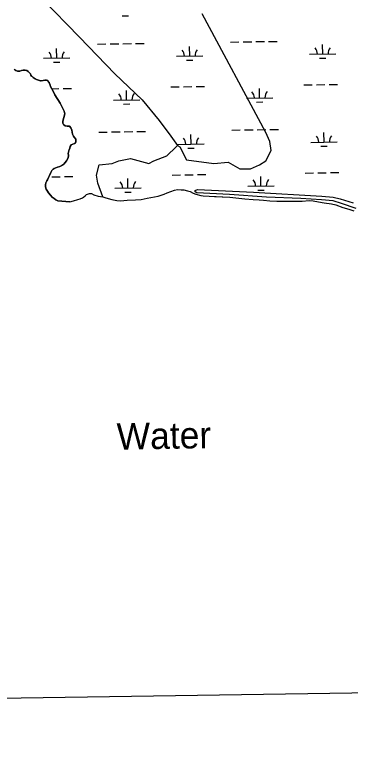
# Model space of a CAD drawing. Extents: x 3812694 to 3850888, y 319753 to 345638.
# Drawn here: x 3828221 to 3829488, y 325178 to 327931 of the extents above; entities that cross this region are included whole.
import ezdxf

# ---------------------------------------------------------------- set-up
doc = ezdxf.new("R2010")
doc.units = 0
for name, color, linetype in [('V-GRID-FRAM', 7, 'Continuous'), ('V-RIVR-IDEN', 7, 'Continuous'), ('V-RIVR-JETY', 7, 'Continuous'), ('V-TOPO-SHOR', 7, 'Continuous'), ('V-WETL-SWMP', 7, 'Continuous')]:
    doc.layers.add(name, color=color, linetype=linetype)

msp = doc.modelspace()

# ---------------------------------------------------------------- linework, layer by layer
at = {"layer": 'V-GRID-FRAM'}
msp.add_lwpolyline([(3816670, 343358.9), (3848499.3, 343840.5), (3848782.3, 325660.2), (3816937.1, 325178.5), (3816670, 343358.9)], dxfattribs=at)
at = {"layer": 'V-RIVR-JETY'}
msp.add_lwpolyline([(3829510.2, 327199.2), (3829453.9, 327218.2), (3829423.1, 327227.1), (3829379.5, 327231.8), (3829300.5, 327236.4), (3829172, 327240.9), (3829032, 327252), (3828908, 327258.4), (3828902, 327262), (3828902, 327267.2), (3828911.2, 327270.6), (3829122.4, 327260), (3829380.5, 327245.1), (3829423.3, 327241.8), (3829450, 327235.5), (3829498.9, 327219.8)], dxfattribs=at)
at = {"layer": 'V-TOPO-SHOR'}
for points in [[(3827576.5, 328656.4), (3827719.1, 328572.8), (3827778.1, 328533.5), (3827832.2, 328474.5), (3827881.4, 328420.4), (3827935.4, 328322.1), (3828033.8, 328248.3), (3828323.8, 327992.7), (3828466.4, 327845.2), (3828599.1, 327707.5), (3828702.4, 327609.2), (3828766.3, 327530.5), (3828810.6, 327471.5), (3828835.1, 327437.1), (3828845, 327432.2)], [(3828845, 327432.2), (3828869.5, 327383), (3828972.8, 327368.3), (3829026.9, 327373.2), (3829071.1, 327348.6), (3829110.5, 327348.6), (3829144.9, 327363.4), (3829169.4, 327378.1), (3829189.1, 327417.4), (3829184.2, 327451.9), (3829169.4, 327486.3), (3828928.5, 327933.7)], [(3828221.8, 327722.9), (3828220.8, 327725.5)], [(3828356.8, 327658.9), (3828354.7, 327664.6), (3828352.1, 327670.2), (3828351.1, 327675.3), (3828349.5, 327676.4), (3828348, 327679.9), (3828346.4, 327681.5), (3828343.9, 327682.5), (3828341.8, 327683), (3828335.6, 327683.5), (3828328.9, 327682.4), (3828321.2, 327680.8), (3828318.2, 327680.3), (3828307.3, 327684.9), (3828303.7, 327685.9), (3828298.6, 327688.9), (3828294.5, 327691.5), (3828291.4, 327693), (3828286.7, 327697.1), (3828284.7, 327699.1), (3828282.6, 327701.7), (3828281, 327706.8), (3828276.4, 327711.9), (3828272.7, 327715.5), (3828267.1, 327719.6), (3828261.4, 327721.1), (3828252.7, 327721.6), (3828247, 327720.5), (3828240.3, 327717.9), (3828235.7, 327716.8), (3828231.6, 327716.8), (3828225.9, 327719.4), (3828221.8, 327722.9)], [(3828428.9, 327224.4), (3828384.4, 327227.3), (3828376.7, 327231.4), (3828370, 327236), (3828362.7, 327241.6), (3828356, 327249.3), (3828349.3, 327258), (3828344.6, 327264.1), (3828340, 327271.3), (3828337.9, 327280.5), (3828337.8, 327287.7), (3828339.3, 327295.4), (3828342.9, 327302.7), (3828345.4, 327307.3), (3828349, 327316.1), (3828352.5, 327323.8), (3828357.1, 327334.6), (3828361.2, 327342.3), (3828366.3, 327347.5), (3828370.4, 327350.1), (3828377, 327352.7), (3828383.2, 327355.3), (3828391.4, 327357.9), (3828399.1, 327361.1), (3828403.7, 327364.2), (3828406.8, 327366.2), (3828410.9, 327371.4), (3828417, 327379.1), (3828421.6, 327387.4), (3828424.6, 327396.1), (3828424.6, 327400.3), (3828423, 327406.4), (3828424, 327410), (3828426, 327417.2), (3828427, 327419.8), (3828429.1, 327426), (3828431.1, 327432.7), (3828434.1, 327439.4), (3828447.5, 327443.6), (3828450.5, 327446.1), (3828452.6, 327450.3), (3828452.5, 327454.4), (3828451.5, 327460), (3828446.3, 327468.2), (3828442.7, 327471.8), (3828439.5, 327480), (3828438.5, 327487.2), (3828436.4, 327494.4), (3828433.2, 327503.6), (3828428.6, 327509.8), (3828425, 327510.2), (3828419.3, 327510.2), (3828411.6, 327510.7), (3828406.5, 327514.3), (3828404.9, 327515.8), (3828403.3, 327520.9), (3828402.8, 327528.1), (3828406.8, 327542), (3828410.3, 327556.4), (3828408.2, 327566.7), (3828393.2, 327595.9), (3828372.4, 327628.2), (3828367.2, 327639.4), (3828361, 327650.7), (3828356.8, 327658.9)], [(3828554, 327242.9), (3828535.2, 327294.5), (3828530.3, 327324), (3828540.2, 327363.4), (3828589.3, 327368.3), (3828613.9, 327378.1), (3828658.1, 327387.9), (3828727, 327368.3), (3828746.6, 327378.1), (3828795.8, 327397.8), (3828830.2, 327432.2), (3828835.1, 327437.1)], [(3828428.9, 327224.4), (3828443.6, 327228.1), (3828459.5, 327233), (3828469, 327235.5), (3828477.2, 327239.1), (3828481.3, 327241.6), (3828487.2, 327246.9), (3828491.9, 327251.1), (3828503.6, 327254.8), (3828510.7, 327254.9), (3828520.3, 327249.7), (3828536.9, 327245.7), (3828554, 327242.9), (3828565.3, 327239.5), (3828588.4, 327233.3), (3828606.2, 327229.3), (3828620.4, 327227.7), (3828645.8, 327229.7), (3828676.6, 327231.3), (3828699, 327233.3), (3828720.8, 327238.2), (3828749.2, 327242.7), (3828762.7, 327245.2), (3828774.5, 327249.5), (3828785.7, 327253.1), (3828796.3, 327258), (3828809.9, 327262.3), (3828824, 327267.7), (3828835.2, 327270.2), (3828849.4, 327269.8), (3828860, 327269.3), (3828873.1, 327265.9), (3828883.2, 327262.5), (3828894.5, 327256.7), (3828905.2, 327253.3), (3828923.5, 327248.1), (3828933, 327246.5), (3828955.5, 327245.5), (3828975, 327244.6), (3829033.6, 327241.6), (3829089.2, 327235.7), (3829121.2, 327232.5), (3829143.7, 327231.6), (3829160.2, 327230.6), (3829184.5, 327227.3), (3829211.1, 327227), (3829266.1, 327226.4), (3829305.8, 327226.3), (3829332.9, 327228.3), (3829347.7, 327227.9), (3829367.3, 327224), (3829388.6, 327220.1), (3829416.4, 327216.2), (3829433, 327212.3), (3829459.7, 327203.1), (3829482.3, 327195.7), (3829501.3, 327189.4)]]:
    msp.add_lwpolyline(points, dxfattribs=at)
at = {"layer": 'V-WETL-SWMP'}
for p, q in [((3828627, 327925.8), (3828651, 327926.2)), ((3828533.7, 327819.8), (3828565.7, 327820.2)), ((3828581.7, 327820.5), (3828613.7, 327821)), ((3828629.7, 327821.2), (3828661.7, 327821.7)), ((3828677.7, 327821.9), (3828709.7, 327822.4)), ((3828881.8, 327774.3), (3828881.2, 327810.3)), ((3829035.6, 327827.4), (3829067.6, 327827.8)), ((3829083.6, 327828.1), (3829115.6, 327828.6)), ((3829131.6, 327828.8), (3829163.6, 327829.3)), ((3829179.6, 327829.5), (3829211.6, 327830)), ((3829383.6, 327781.9), (3829383.1, 327817.9)), ((3828379.9, 327766.7), (3828379.4, 327802.7)), ((3829333.6, 327781.1), (3829433.6, 327782.6)), ((3828329.9, 327765.9), (3828429.9, 327767.4)), ((3828368.2, 327751.1), (3828392.2, 327751.4)), ((3828831.8, 327773.5), (3828931.8, 327775)), ((3828870, 327758.7), (3828894, 327759)), ((3829371.9, 327766.3), (3829395.9, 327766.6)), ((3828220.8, 327725.5), (3828221.8, 327722.9)), ((3828221.8, 327722.9), (3828225.9, 327719.4)), ((3828225.9, 327719.4), (3828231.6, 327716.8)), ((3828231.6, 327716.8), (3828235.7, 327716.8)), ((3828235.7, 327716.8), (3828240.3, 327717.9)), ((3828240.3, 327717.9), (3828247, 327720.5)), ((3828247, 327720.5), (3828252.7, 327721.6)), ((3828252.7, 327721.6), (3828261.4, 327721.1)), ((3828261.4, 327721.1), (3828267.1, 327719.6)), ((3828267.1, 327719.6), (3828272.7, 327715.5)), ((3828272.7, 327715.5), (3828276.4, 327711.9)), ((3828276.4, 327711.9), (3828281, 327706.8)), ((3828281, 327706.8), (3828282.6, 327701.7)), ((3828282.6, 327701.7), (3828284.7, 327699.1)), ((3828284.7, 327699.1), (3828286.7, 327697.1)), ((3828286.7, 327697.1), (3828291.4, 327693)), ((3828291.4, 327693), (3828294.5, 327691.5)), ((3828294.5, 327691.5), (3828298.6, 327688.9)), ((3828298.6, 327688.9), (3828303.7, 327685.9)), ((3828303.7, 327685.9), (3828307.3, 327684.9)), ((3828307.3, 327684.9), (3828318.2, 327680.3)), ((3828318.2, 327680.3), (3828321.2, 327680.8)), ((3828321.2, 327680.8), (3828328.9, 327682.4)), ((3828328.9, 327682.4), (3828335.6, 327683.5)), ((3828335.6, 327683.5), (3828341.8, 327683)), ((3828341.8, 327683), (3828343.9, 327682.5)), ((3828343.9, 327682.5), (3828346.4, 327681.5)), ((3828346.4, 327681.5), (3828348, 327679.9)), ((3828348, 327679.9), (3828349.5, 327676.4)), ((3828349.5, 327676.4), (3828351.1, 327675.3)), ((3828351.1, 327675.3), (3828352.1, 327670.2)), ((3828352.1, 327670.2), (3828354.7, 327664.6)), ((3828354.7, 327664.6), (3828356.8, 327658.9)), ((3828356.8, 327658.9), (3828361, 327650.7)), ((3828360.9, 327651), (3828388.3, 327651.4)), ((3828361, 327650.7), (3828367.2, 327639.4)), ((3828404.3, 327651.6), (3828436.3, 327652.1)), ((3828643.8, 327608.8), (3828643.2, 327644.8)), ((3828810.1, 327657.8), (3828842.1, 327658.2)), ((3828858.1, 327658.5), (3828890.1, 327659)), ((3828906.1, 327659.2), (3828938.1, 327659.7)), ((3829145.6, 327616.4), (3829145.1, 327652.4)), ((3829312, 327665.3), (3829344, 327665.8)), ((3829360, 327666.1), (3829392, 327666.6)), ((3829408, 327666.8), (3829440, 327667.3)), ((3828367.2, 327639.4), (3828372.4, 327628.2)), ((3828372.4, 327628.2), (3828393.2, 327595.9)), ((3829095.6, 327615.6), (3829195.6, 327617.1)), ((3828393.2, 327595.9), (3828408.2, 327566.7)), ((3828593.8, 327608), (3828693.8, 327609.6)), ((3828632, 327593.2), (3828656, 327593.6)), ((3829133.9, 327600.8), (3829157.9, 327601.1)), ((3828408.2, 327566.7), (3828410.3, 327556.4)), ((3828406.8, 327542), (3828402.8, 327528.1)), ((3828410.3, 327556.4), (3828406.8, 327542)), ((3828402.8, 327528.1), (3828403.3, 327520.9)), ((3828403.3, 327520.9), (3828404.9, 327515.8)), ((3828404.9, 327515.8), (3828406.5, 327514.3)), ((3828406.5, 327514.3), (3828411.6, 327510.7)), ((3828411.6, 327510.7), (3828419.3, 327510.2)), ((3828419.3, 327510.2), (3828425, 327510.2)), ((3828425, 327510.2), (3828428.6, 327509.8)), ((3828428.6, 327509.8), (3828433.2, 327503.6)), ((3828433.2, 327503.6), (3828436.4, 327494.4)), ((3828436.4, 327494.4), (3828438.5, 327487.2)), ((3828438.5, 327487.2), (3828439.5, 327480)), ((3828439.5, 327480), (3828442.7, 327471.8)), ((3828538.8, 327487.1), (3828570.8, 327487.6)), ((3828586.8, 327487.9), (3828618.8, 327488.3)), ((3828634.8, 327488.6), (3828666.8, 327489.1)), ((3828682.7, 327489.3), (3828714.7, 327489.8)), ((3828886.8, 327441.6), (3828886.3, 327477.6)), ((3829040.6, 327494.7), (3829072.6, 327495.2)), ((3829088.6, 327495.4), (3829120.6, 327495.9)), ((3829136.6, 327496.2), (3829168.6, 327496.7)), ((3829184.6, 327496.9), (3829216.6, 327497.4)), ((3829388.7, 327449.2), (3829388.1, 327485.2)), ((3828442.7, 327471.8), (3828446.3, 327468.2)), ((3828446.3, 327468.2), (3828451.5, 327460)), ((3828452.6, 327450.3), (3828450.5, 327446.1)), ((3828451.5, 327460), (3828452.5, 327454.4)), ((3828452.5, 327454.4), (3828452.6, 327450.3)), ((3829338.7, 327448.5), (3829438.7, 327450)), ((3828429.1, 327426), (3828427, 327419.8)), ((3828431.1, 327432.7), (3828429.1, 327426)), ((3828434.1, 327439.4), (3828431.1, 327432.7)), ((3828432, 327434.8), (3828435, 327434.8)), ((3828447.5, 327443.6), (3828434.1, 327439.4)), ((3828450.5, 327446.1), (3828447.5, 327443.6)), ((3828836.8, 327440.9), (3828936.8, 327442.4)), ((3828875, 327426), (3828899, 327426.4)), ((3829376.9, 327433.6), (3829400.9, 327434)), ((3828424.6, 327396.1), (3828421.6, 327387.4)), ((3828426, 327417.2), (3828423, 327406.4)), ((3828423, 327406.4), (3828424.6, 327400.3)), ((3828424.6, 327400.3), (3828424.6, 327396.1)), ((3828427, 327419.8), (3828426, 327417.2)), ((3828406.8, 327366.2), (3828399.1, 327361.1)), ((3828417, 327379.1), (3828406.8, 327366.2)), ((3828421.6, 327387.4), (3828417, 327379.1)), ((3828361.2, 327342.3), (3828357.1, 327334.6)), ((3828366.3, 327347.5), (3828361.2, 327342.3)), ((3828370.4, 327350.1), (3828366.3, 327347.5)), ((3828377, 327352.7), (3828370.4, 327350.1)), ((3828383.2, 327355.3), (3828377, 327352.7)), ((3828391.4, 327357.9), (3828383.2, 327355.3)), ((3828399.1, 327361.1), (3828391.4, 327357.9)), ((3828349, 327316.1), (3828345.4, 327307.3)), ((3828352.5, 327323.8), (3828349, 327316.1)), ((3828357.1, 327334.6), (3828352.5, 327323.8)), ((3828361.3, 327318.2), (3828393.3, 327318.7)), ((3828409.3, 327319), (3828441.3, 327319.5)), ((3828648.8, 327276.2), (3828648.3, 327312.2)), ((3828815.2, 327325.1), (3828847.2, 327325.6)), ((3828863.2, 327325.8), (3828895.1, 327326.3)), ((3828911.1, 327326.6), (3828943.1, 327327)), ((3829150.7, 327283.8), (3829150.1, 327319.7)), ((3829317, 327332.7), (3829349, 327333.2)), ((3829365, 327333.4), (3829397, 327333.9)), ((3829413, 327334.2), (3829445, 327334.6)), ((3828339.3, 327295.4), (3828337.8, 327287.7)), ((3828337.8, 327287.7), (3828337.9, 327280.5)), ((3828342.9, 327302.7), (3828339.3, 327295.4)), ((3828345.4, 327307.3), (3828342.9, 327302.7)), ((3829100.7, 327283), (3829200.7, 327284.5)), ((3828337.9, 327280.5), (3828340, 327271.3)), ((3828340, 327271.3), (3828344.6, 327264.1)), ((3828344.6, 327264.1), (3828349.3, 327258)), ((3828349.3, 327258), (3828356, 327249.3)), ((3828491.9, 327251.1), (3828503.6, 327254.8)), ((3828503.6, 327254.8), (3828510.7, 327254.9)), ((3828510.7, 327254.9), (3828520.3, 327249.7)), ((3828598.8, 327275.4), (3828698.8, 327276.9)), ((3828637, 327260.6), (3828661, 327260.9)), ((3828785.7, 327253.1), (3828796.3, 327258)), ((3828796.3, 327258), (3828809.9, 327262.3)), ((3828809.9, 327262.3), (3828824, 327267.7)), ((3828824, 327267.7), (3828835.2, 327270.2)), ((3828835.2, 327270.2), (3828849.4, 327269.8)), ((3828849.4, 327269.8), (3828860, 327269.3)), ((3828860, 327269.3), (3828873.1, 327265.9)), ((3828873.1, 327265.9), (3828883.2, 327262.5)), ((3828883.2, 327262.5), (3828894.5, 327256.7)), ((3828894.5, 327256.7), (3828905.2, 327253.3)), ((3829138.9, 327268.1), (3829162.9, 327268.5)), ((3828356, 327249.3), (3828362.7, 327241.6)), ((3828362.7, 327241.6), (3828370, 327236)), ((3828370, 327236), (3828376.7, 327231.4)), ((3828376.7, 327231.4), (3828384.4, 327227.3)), ((3828384.4, 327227.3), (3828428.9, 327224.4)), ((3828428.9, 327224.4), (3828443.6, 327228.1)), ((3828443.6, 327228.1), (3828459.5, 327233)), ((3828459.5, 327233), (3828469, 327235.5)), ((3828469, 327235.5), (3828477.2, 327239.1)), ((3828477.2, 327239.1), (3828481.3, 327241.6)), ((3828481.3, 327241.6), (3828487.2, 327246.9)), ((3828487.2, 327246.9), (3828491.9, 327251.1)), ((3828520.3, 327249.7), (3828536.9, 327245.7)), ((3828536.9, 327245.7), (3828554, 327242.9)), ((3828554, 327242.9), (3828565.3, 327239.5)), ((3828565.3, 327239.5), (3828588.4, 327233.3)), ((3828588.4, 327233.3), (3828606.2, 327229.3)), ((3828606.2, 327229.3), (3828620.4, 327227.7)), ((3828620.4, 327227.7), (3828645.8, 327229.7)), ((3828645.8, 327229.7), (3828676.6, 327231.3)), ((3828676.6, 327231.3), (3828699, 327233.3)), ((3828699, 327233.3), (3828720.8, 327238.2)), ((3828720.8, 327238.2), (3828749.2, 327242.7)), ((3828749.2, 327242.7), (3828762.7, 327245.2)), ((3828762.7, 327245.2), (3828774.5, 327249.5)), ((3828774.5, 327249.5), (3828785.7, 327253.1)), ((3828905.2, 327253.3), (3828923.5, 327248.1)), ((3828923.5, 327248.1), (3828933, 327246.5)), ((3828933, 327246.5), (3828955.5, 327245.5)), ((3828955.5, 327245.5), (3829033.6, 327241.6)), ((3829033.6, 327241.6), (3829089.2, 327235.7)), ((3829089.2, 327235.7), (3829121.2, 327232.5)), ((3829121.2, 327232.5), (3829143.7, 327231.6)), ((3829143.7, 327231.6), (3829160.2, 327230.6)), ((3829160.2, 327230.6), (3829184.5, 327227.3)), ((3829184.5, 327227.3), (3829211.1, 327227)), ((3829305.8, 327226.3), (3829332.9, 327228.3)), ((3829332.9, 327228.3), (3829347.7, 327227.9)), ((3829347.7, 327227.9), (3829367.3, 327224)), ((3829211.1, 327227), (3829266.1, 327226.4)), ((3829266.1, 327226.4), (3829305.8, 327226.3)), ((3829367.3, 327224), (3829388.6, 327220.1)), ((3829388.6, 327220.1), (3829416.4, 327216.2)), ((3829416.4, 327216.2), (3829433, 327212.3)), ((3829433, 327212.3), (3829459.7, 327203.1)), ((3829459.7, 327203.1), (3829482.3, 327195.7)), ((3829482.3, 327195.7), (3829501.3, 327189.4))]:
    msp.add_line(p, q, dxfattribs=at)
for centre, start, end in [((3829438.9, 327783.2), 140.0949, 181.6385), ((3828324.7, 327766.3), 0.0949, 41.6385), ((3828435.2, 327768), 140.0949, 181.6385), ((3828826.5, 327773.9), 0.0949, 41.6385), ((3828937, 327775.6), 140.0949, 181.6385), ((3829328.4, 327781.5), 0.0949, 41.6385), ((3829200.9, 327617.7), 140.0949, 181.6385), ((3828588.5, 327608.4), 0.0949, 41.6385), ((3828699, 327610.1), 140.0949, 181.6385), ((3829090.4, 327616), 0.0949, 41.6385), ((3828831.6, 327441.3), 0.0949, 41.6385), ((3828942, 327443), 140.0949, 181.6385), ((3829333.4, 327448.9), 0.0949, 41.6385), ((3829443.9, 327450.5), 140.0949, 181.6385), ((3828593.6, 327275.8), 0.0949, 41.6385), ((3828704, 327277.5), 140.0949, 181.6385), ((3829095.4, 327283.4), 0.0949, 41.6385), ((3829205.9, 327285.1), 140.0949, 181.6385)]:
    msp.add_arc(centre, 35.2, start, end, dxfattribs=at)

# ---------------------------------------------------------------- texts
at = {"layer": 'V-RIVR-IDEN'}
msp.add_text('Water', height=100, rotation=0.975, dxfattribs=at).set_placement((3828606.9, 326287.8))

doc.saveas('drawing.dxf')
